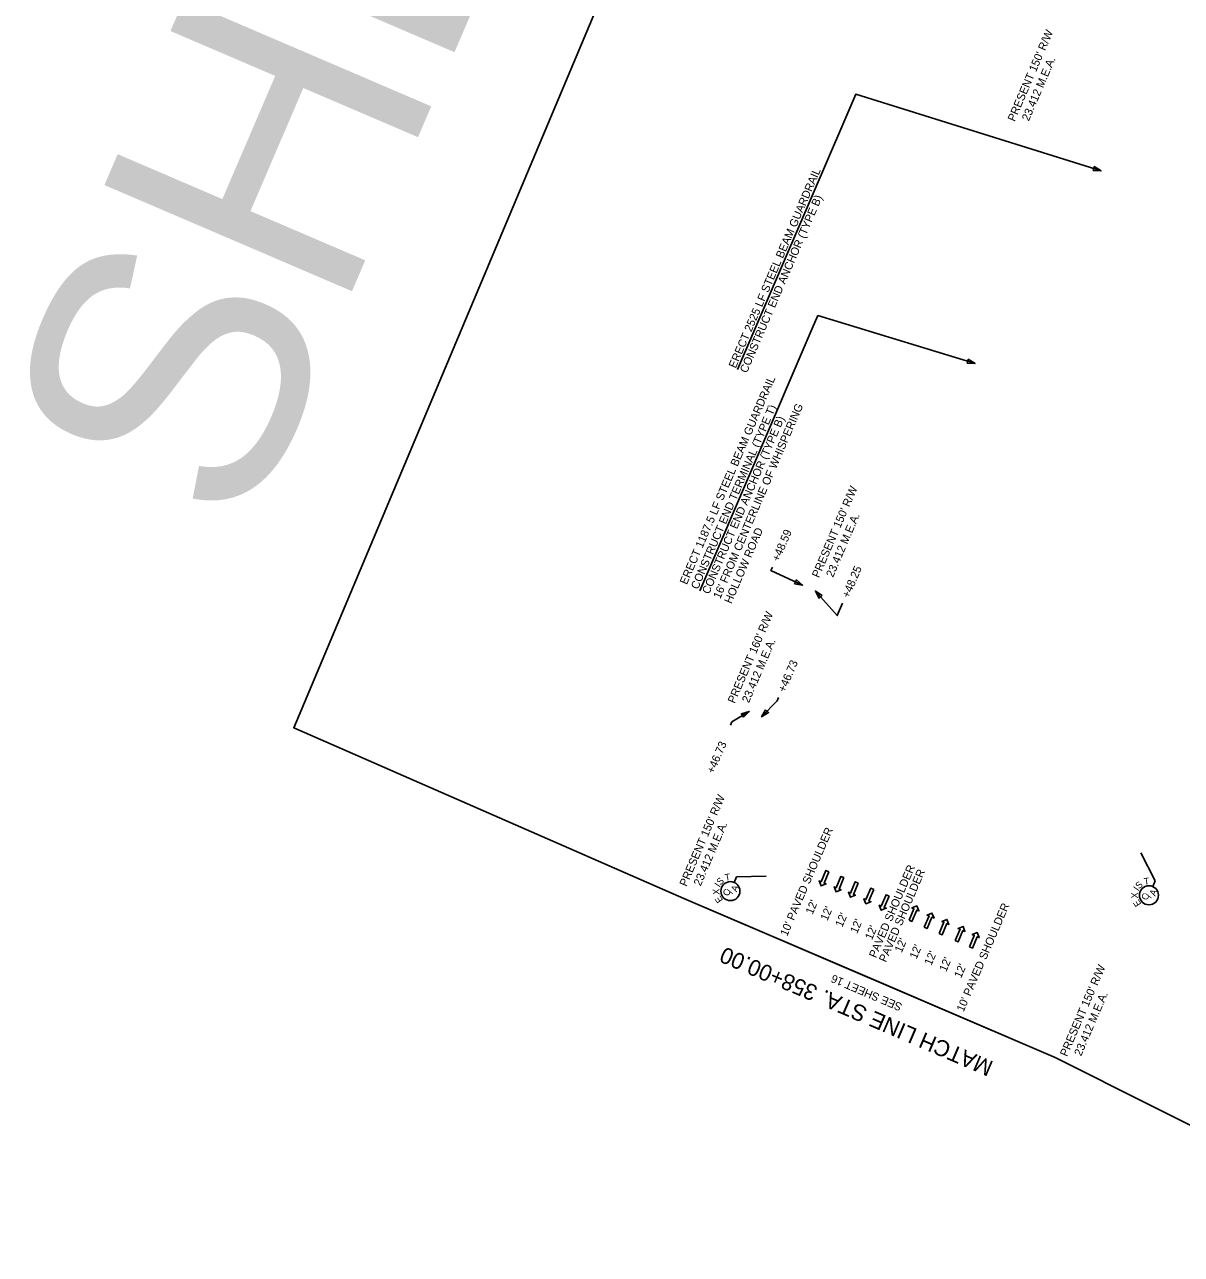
# Model space of a CAD drawing. Extents: x 1615013 to 1616950, y 1098171 to 1100198.
# Drawn here: x 1615013 to 1615872, y 1098243 to 1099157 of the extents above; entities that cross this region are included whole.
import ezdxf

# ---------------------------------------------------------------- set-up
doc = ezdxf.new("R2010")
doc.units = 0
for name, color, linetype in [('RD_DTM_Obscure', 7, 'Continuous'), ('RD_EX_BldgApp', 7, 'Continuous'), ('RD_EX_Driveway', 7, 'Continuous'), ('RD_EX_Misc', 7, 'Continuous'), ('RD_EX_Misc_Golf_Teebox', 7, 'Continuous'), ('RD_EX_Road', 7, 'Continuous'), ('RD_EX_UT', 7, 'Continuous'), ('RD_EX_VEG', 7, 'Continuous')]:
    doc.layers.add(name, color=color, linetype=linetype)

msp = doc.modelspace()

# ---------------------------------------------------------------- linework, layer by layer
at = {"layer": 'RD_DTM_Obscure'}
for p, q in [((1615852.7, 1098520.9), (1615842.15, 1098541.66)), ((1615540.12, 1098519.79), (1615541.92, 1098523.99)), ((1615541.92, 1098523.99), (1615563.78, 1098524.36)), ((1615850.89, 1098516.69), (1615852.7, 1098520.9))]:
    msp.add_line(p, q, dxfattribs=at)
for centre in [(1615537.33, 1098513.27), (1615848.1, 1098510.18)]:
    msp.add_circle(centre, 7.08, dxfattribs=at)
at = {"layer": 'RD_EX_BldgApp'}
for points in [[(1615568.57, 1098753.96), (1615567.42, 1098751.27), (1615590.94, 1098740.56)], [(1615620.62, 1098727.03), (1615616.69, 1098717.85), (1615600.53, 1098736.08)], [(1615573.16, 1098657.05), (1615572.11, 1098654.6), (1615560.54, 1098642.77)], [(1615537.33, 1098636.52), (1615538.34, 1098638.88), (1615551.35, 1098646.71)]]:
    msp.add_lwpolyline(points, dxfattribs=at)
for points in [[(1615585.02, 1098741.55), (1615590.94, 1098740.56), (1615586.31, 1098744.38)], [(1615605.54, 1098732.78), (1615600.53, 1098736.08), (1615603.21, 1098730.72)], [(1615547.18, 1098642.39), (1615551.35, 1098646.71), (1615545.58, 1098645.05)], [(1615563.48, 1098648), (1615560.54, 1098642.77), (1615565.7, 1098645.82)]]:
    msp.add_lwpolyline(points, close=True, dxfattribs=at)
at = {"layer": 'RD_EX_Driveway'}
for p, q in [((1615621.47, 1099084.33), (1615542.66, 1098900.58)), ((1615598.12, 1098931.04), (1615514.62, 1098736.35))]:
    msp.add_line(p, q, dxfattribs=at)
for points in [[(1615621.47, 1099084.33), (1615630.38, 1099105.09), (1615812.6, 1099048.16)], [(1615598.12, 1098931.04), (1615602.27, 1098940.72), (1615719.07, 1098905.06)]]:
    msp.add_lwpolyline(points, dxfattribs=at)
for points in [[(1615806.61, 1099048.4), (1615812.6, 1099048.16), (1615807.54, 1099051.37)], [(1615713.07, 1098905.27), (1615719.07, 1098905.06), (1615713.98, 1098908.24)]]:
    msp.add_lwpolyline(points, close=True, dxfattribs=at)
at = {"layer": 'RD_EX_Misc'}
for points in [[(1615610.48, 1098527.66), (1615608.27, 1098528.6), (1615604.66, 1098520.18), (1615603.16, 1098520.82), (1615604.64, 1098517.1), (1615608.36, 1098518.59), (1615606.86, 1098519.23)], [(1615621.63, 1098523.27), (1615619.42, 1098524.21), (1615615.8, 1098515.79), (1615614.31, 1098516.43), (1615615.79, 1098512.71), (1615619.51, 1098514.2), (1615618.01, 1098514.84)], [(1615632.27, 1098519.22), (1615630.06, 1098520.17), (1615626.44, 1098511.74), (1615624.95, 1098512.39), (1615626.43, 1098508.67), (1615630.15, 1098510.15), (1615628.65, 1098510.8)], [(1615632.27, 1098519.22), (1615630.06, 1098520.17), (1615626.44, 1098511.74), (1615624.95, 1098512.39), (1615626.43, 1098508.67), (1615630.15, 1098510.15), (1615628.65, 1098510.8)], [(1615643.77, 1098514.43), (1615641.57, 1098515.37), (1615637.95, 1098506.94), (1615636.45, 1098507.59), (1615637.93, 1098503.87), (1615641.65, 1098505.36), (1615640.15, 1098506)], [(1615643.77, 1098514.43), (1615641.57, 1098515.37), (1615637.95, 1098506.94), (1615636.45, 1098507.59), (1615637.93, 1098503.87), (1615641.65, 1098505.36), (1615640.15, 1098506)], [(1615655.13, 1098509.59), (1615652.92, 1098510.53), (1615649.3, 1098502.1), (1615647.81, 1098502.75), (1615649.29, 1098499.03), (1615653.01, 1098500.52), (1615651.51, 1098501.16)], [(1615655.13, 1098509.59), (1615652.92, 1098510.53), (1615649.3, 1098502.1), (1615647.81, 1098502.75), (1615649.29, 1098499.03), (1615653.01, 1098500.52), (1615651.51, 1098501.16)], [(1615669.96, 1098491.68), (1615672.17, 1098490.73), (1615675.77, 1098499.17), (1615677.27, 1098498.53), (1615675.77, 1098502.24), (1615672.06, 1098500.75), (1615673.56, 1098500.11)], [(1615681.22, 1098486.4), (1615683.43, 1098485.46), (1615687.02, 1098493.9), (1615688.52, 1098493.26), (1615687.03, 1098496.97), (1615683.32, 1098495.48), (1615684.82, 1098494.84)], [(1615692.26, 1098481.7), (1615694.47, 1098480.76), (1615698.06, 1098489.19), (1615699.56, 1098488.55), (1615698.07, 1098492.27), (1615694.36, 1098490.77), (1615695.86, 1098490.13)], [(1615704.19, 1098476.48), (1615706.39, 1098475.52), (1615710.04, 1098483.94), (1615711.53, 1098483.29), (1615710.06, 1098487.01), (1615706.34, 1098485.54), (1615707.83, 1098484.89)], [(1615714.78, 1098471.93), (1615716.99, 1098470.98), (1615720.63, 1098479.4), (1615722.12, 1098478.75), (1615720.65, 1098482.47), (1615716.93, 1098481), (1615718.43, 1098480.35)]]:
    msp.add_lwpolyline(points, close=True, dxfattribs=at)
at = {"layer": 'RD_EX_Misc_Golf_Teebox'}
msp.add_line((1615647.02, 1098463.86), (1615647.02, 1098463.86), dxfattribs=at)
at = {"layer": 'RD_EX_UT'}
msp.add_lwpolyline([(1615502.74, 1098507.9), (1615778.49, 1098389.73), (1616070.13, 1098243.47), (1616662.91, 1099630.34), (1616368.69, 1099765.81), (1616095.11, 1099888.91), (1615859.04, 1099986.01), (1615829.52, 1100008.42), (1615766.4, 1099858.36), (1615733.68, 1099872.12), (1615213.09, 1098634.6)], close=True, dxfattribs=at)
msp.add_lwpolyline([(1615502.74, 1098507.9), (1615778.49, 1098389.73), (1616070.13, 1098243.47), (1616662.91, 1099630.34), (1616368.69, 1099765.81), (1616095.11, 1099888.91), (1615859.04, 1099986.01), (1615829.52, 1100008.42), (1615766.4, 1099858.36), (1615733.68, 1099872.12), (1615213.09, 1098634.6)], close=True, dxfattribs=at)
at = {"layer": 'RD_EX_VEG'}
msp.add_lwpolyline([(1615778.49, 1098389.73), (1615640.62, 1098448.82), (1615502.74, 1098507.9)], dxfattribs=at)

# ---------------------------------------------------------------- texts
at = {"layer": 'RD_DTM_Obscure'}
for s, rotation, p in [('T', 9.83471, (1615533.62, 1098520.83)), ('I', 56.71668, (1615529.28, 1098515.73)), ('S', 44.99618, (1615529.94, 1098517.32)), ('A', 66.78137, (1615541.97, 1098512.3)), ('I', 54.76452, (1615840.14, 1098512.92)), ('S', 43.04403, (1615840.86, 1098514.48)), ('T', 7.88256, (1615844.65, 1098517.87)), ('X', 91.87815, (1615529.33, 1098510.65)), ('E', 125.36527, (1615532.11, 1098506.67)), ('C', 66.78137, (1615535.97, 1098509.12)), ('/', 66.78137, (1615539.07, 1098511.01)), ('X', 89.926, (1615840.01, 1098507.83)), ('C', 66.78137, (1615846.74, 1098506.03)), ('/', 66.78137, (1615849.85, 1098507.91)), ('A', 66.78137, (1615852.74, 1098509.21)), ('E', 123.41311, (1615842.65, 1098503.76))]:
    msp.add_text(s, height=5, rotation=rotation, dxfattribs=at).set_placement(p)
at = {"layer": 'RD_EX_BldgApp'}
for s, p in [("PRESENT 150' R/W ", (1615748.41, 1099084.37)), ('  23.412 M.E.A.', (1615757.15, 1099080.62)), ("PRESENT 150' R/W ", (1615603.08, 1098745.52)), ('  23.412 M.E.A.', (1615611.81, 1098741.77)), ('+48.59', (1615573.36, 1098757.5)), ('+48.25', (1615625.35, 1098730.44)), ("PRESENT 160' R/W ", (1615540.56, 1098652.24)), ('  23.412 M.E.A.', (1615549.29, 1098648.5)), ('+46.73', (1615577.89, 1098660.46)), ('+46.73', (1615524.98, 1098600.1)), ("PRESENT 150' R/W ", (1615504.74, 1098516.25)), ('  23.412 M.E.A.', (1615513.47, 1098512.5)), ("PRESENT 150' R/W ", (1615787.26, 1098389.98)), ('  23.412 M.E.A.', (1615795.99, 1098386.24))]:
    msp.add_text(s, height=6, rotation=66.78463, dxfattribs=at).set_placement(p)
at = {"layer": 'RD_EX_Driveway'}
for s, p in [('ERECT 2525 LF STEEL BEAM GUARDRAIL', (1615541.29, 1098901.17)), ('CONSTRUCT END ANCHOR (TYPE B)', (1615549.56, 1098897.62)), ('ERECT 1187.5 LF STEEL BEAM GUARDRAIL', (1615504.97, 1098740.49)), ('CONSTRUCT END TERMINAL (TYPE T)', (1615513.24, 1098736.94)), ("16' FROM CENTERLINE OF WHISPERING", (1615529.79, 1098729.85)), ('CONSTRUCT END ANCHOR (TYPE B)', (1615521.51, 1098733.39)), ('HOLLOW ROAD', (1615538.06, 1098726.3))]:
    msp.add_text(s, height=6, rotation=66.78626, dxfattribs=at).set_placement(p)
at = {"layer": 'RD_EX_Misc_Golf_Teebox'}
for s, rotation, p in [("10' PAVED SHOULDER", 66.78463, (1615579.45, 1098479.33)), (' PAVED SHOULDER', 66.78463, (1615644.56, 1098461.13)), (' PAVED SHOULDER', 66.78463, (1615651.99, 1098457.94)), ("12'", 66.783, (1615598.32, 1098495.48)), ("12'", 66.783, (1615609.35, 1098490.75)), ("10' PAVED SHOULDER", 66.78463, (1615710.49, 1098423.13)), ("12'", 66.783, (1615620.38, 1098486.02)), ("12'", 66.783, (1615631.41, 1098481.29)), ("12'", 66.783, (1615642.43, 1098476.56)), ("12'", 66.783, (1615664.49, 1098467.1)), ("12'", 66.783, (1615675.52, 1098462.37)), ("12'", 66.783, (1615686.55, 1098457.64)), ("12'", 66.783, (1615697.58, 1098452.91)), ("12'", 66.783, (1615708.6, 1098448.17))]:
    msp.add_text(s, height=6, rotation=rotation, dxfattribs=at).set_placement(p)
at = {"layer": 'RD_EX_Road'}
msp.add_text('SHEET 17', height=200, rotation=66.78463, dxfattribs=at).set_placement((1615177.39, 1098774.72))
at = {"layer": 'RD_EX_VEG'}
for s, height, rotation, p in [('MATCH LINE STA. 358+00.00', 12, 156.80236, (1615733.4, 1098386.39)), ('SEE SHEET 16', 6, 156.8359, (1615665.43, 1098429.41))]:
    msp.add_text(s, height=height, rotation=rotation, dxfattribs=at).set_placement(p)

doc.saveas('drawing.dxf')
